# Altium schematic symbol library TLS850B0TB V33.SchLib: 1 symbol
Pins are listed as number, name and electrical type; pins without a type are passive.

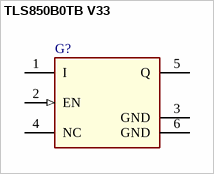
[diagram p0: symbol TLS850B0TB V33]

## TLS850B0TB V33
designator G?  (value not drawn)
Low Dropout Linear Voltage Regulator, Fixed output voltage 3.3 V, Output voltage accuracy ≤ ±2%; Manufacturer: Infineon Technologies
footprint TO170P1500X450-6N
pins: 1 I (power) "Input", 2 EN (in) "Enable", 3 GND (power) "Ground", 4 NC "Not connected", 5 Q (power) "Output", 6 GND (power) "Heat Slug"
